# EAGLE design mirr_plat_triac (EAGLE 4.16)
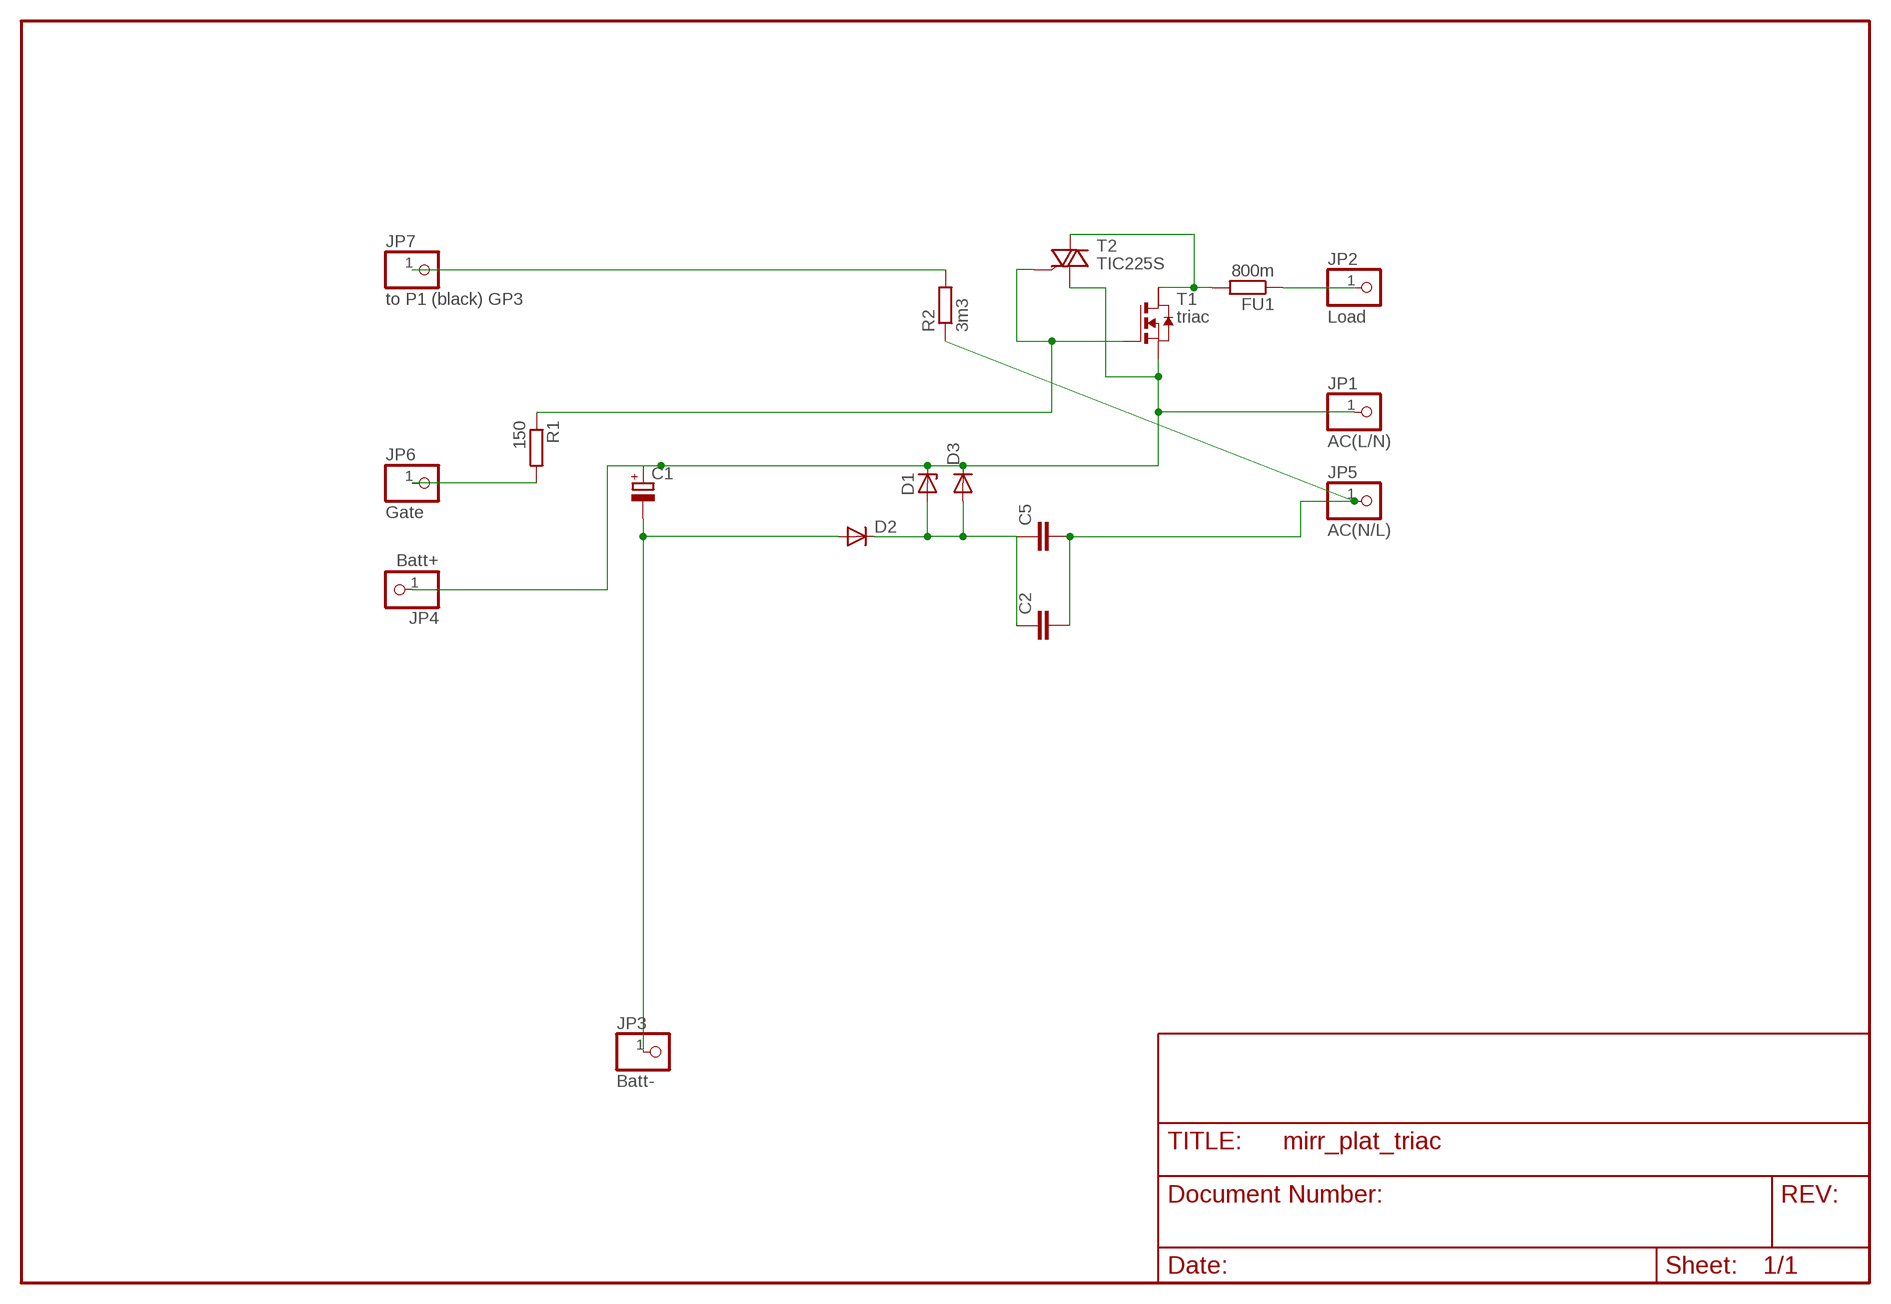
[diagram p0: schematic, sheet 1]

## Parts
C1  CPOL-EUE2,5-6E  [E2,5-6E]
C2  C-EU102-043X133  [C102-043X133]
C5  C-EU050-025X075  [C050-025X075]
D1  ZENER-DIODEDO35Z10  [DO35Z10]
D2  DIODE-MELF-MLL41  [MELF-MLL41]
D3  DIODE-MINIMELF  [MINIMELF]
FU1  800m  R-EU_0204/5  [0204/5]
JP1  AC(L/N)  PINHD-1X1  [1X01]
JP2  Load  PINHD-1X1  [1X01]
JP3  Batt-  PINHD-1X1  [1X01]
JP4  Batt+  PINHD-1X1  [1X01]
JP5  AC(N/L)  PINHD-1X1  [1X01]
JP6  Gate  PINHD-1X1  [1X01]
JP7  to P1 (black) GP3  PINHD-1X1  [1X01]
R1  150  R-EU_R1206  [R1206]
R2  3m3  R-EU_R1206  [R1206]
T1  triac  NMOSSOT223  [SOT223]
T2  TIC225S  [TO220DS]

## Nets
N$1: C1.+ D1.C D3.C JP1.1 JP4.1 T1.3(S) T2.A1
N$2: R1.1 T1.1(G) T2.G
N$3: C1.- D2.A JP3.1
N$4: FU1.1 JP2.1
N$5: JP7.1 R2.2
N$6: C2.1 C5.1 D1.A D2.C D3.A
N$9: FU1.2 T1.2(D) T2.A2
N$11: JP6.1 R1.2
N$37: C2.2 C5.2 JP5.1 R2.1
Unconnected: T1.4(D2)

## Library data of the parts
C1 = rcl(2):CPOL-EU: POLARIZED CAPACITOR, European symbol
C2 = rcl-2:C-EU: CAPACITOR, European symbol
C5 = rcl:C-EU: CAPACITOR, European symbol
D1 = diode-1:ZENER-DIODE: Z-Diode
D2 D3 = diode-1:DIODE-: DIODE
FU1 R1 R2 = rcl:R-EU_: RESISTOR, European symbol
JP1-JP7 = pinhead:PINHD-1X1: PIN HEADER
T1 = zetex:NMOSSOT223: MOS FET
T2 = triac:TIC225S: TRIAC

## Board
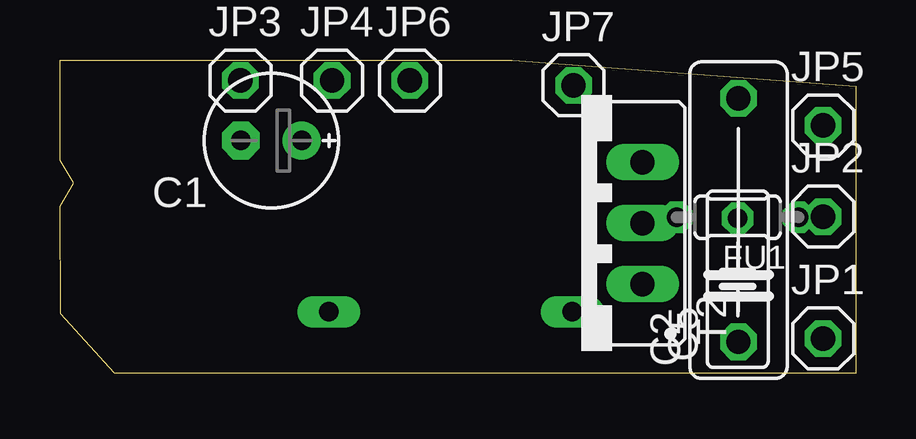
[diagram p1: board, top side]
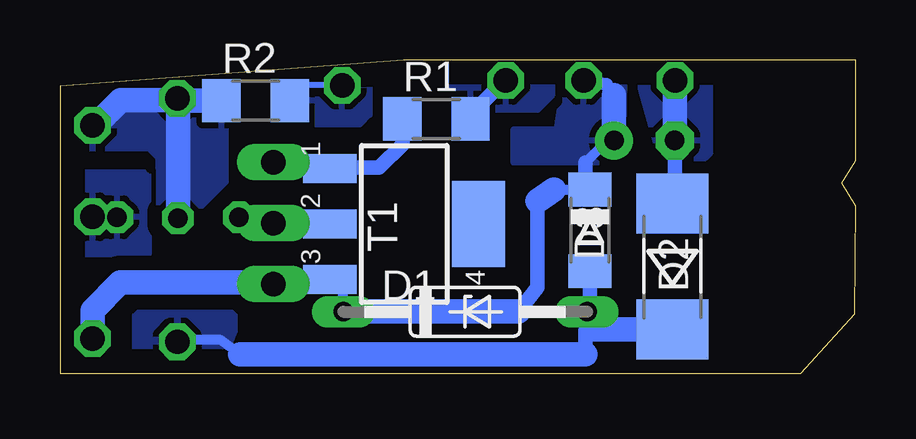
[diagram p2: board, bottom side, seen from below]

Size 33.17 x 13.08 mm. Coordinates in mm from the lower left corner, seen from the top.
Outline: 33.17,0.01 2.29,0 2.29,0.01 0.04,2.48 0,6.99 0.57,7.94 0,8.89 0,13.08 15.18,13.08 18.86,13.08 33.17,12 33.17,0.01
Copper layers (1*16): Top 0.035mm / dielectric 1.5mm / Bottom 0.035mm
Design rules "default": minimum track width 10mil, minimum drill 24mil, track to track 8mil, track to pad 8mil, pad to pad 8mil, via to via 8mil, smd to smd 8mil, copper to edge 40mil, drill to drill 8mil, minimum pad ring 10mil, minimum via ring 8mil, stop-mask expansion 4mil, vias tented up to drill 0mil, thermal gap 10mil

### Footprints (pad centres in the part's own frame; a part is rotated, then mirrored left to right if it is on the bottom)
E2,5-6E = drill 0.813 pad 1.575 round: + -1.27,0 | drill 0.813 pad 1.575 octagon: - 1.27,0
C102-043X133 = drill 1.016 octagon: 1 -5.08,0; 2 5.08,0
C050-025X075 = drill 0.813 octagon: 1 -2.54,0; 2 2.54,0
DO35Z10 = drill 0.813 long: A 5.08,0; C -5.08,0
MELF-MLL41 = smd 2.5 x 3: A 2.625,0; C -2.625,0
MINIMELF = smd 1.4 x 1.8: A 1.7,0; C -1.7,0
0204/5 = drill 0.813 octagon: 1 -2.54,0; 2 2.54,0
1X01 = drill 1.016 octagon: 1 0,0
R1206 = smd 1.6 x 1.803: 1 -1.422,0; 2 1.422,0
SOT223 = smd 1.219 x 2.235: 1 -2.311,-3.099; 2 0,-3.099; 3 2.311,-3.099 | smd 3.6 x 2.2: 4 0,3.099
TO220DS = drill 1.016 long: A1 -2.54,-2.54; A2 0,-2.54; G 2.54,-2.54

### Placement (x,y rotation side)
C1  8.81,9.72 180 top
C2  28.28,6.4 90 top
C5  28.25,3.94 90 top
D1  16.28,2.58 0 bottom
D2  7.64,4.47 90 bottom
D3  11.08,5.98 270 bottom
FU1  28.25,6.52 180 top
JP1  31.81,1.46 0 top
JP2  31.81,6.54 0 top
JP3  7.53,12.23 0 top
JP4  11.34,12.22 0 top
JP5  31.81,10.35 0 top
JP6  14.59,12.22 0 top
JP7  21.41,12.02 0 top
R1  17.48,10.62 0 bottom
R2  25.02,11.39 0 bottom
T1  18.82,6.24 270 bottom
T2  21.74,6.27 90 top

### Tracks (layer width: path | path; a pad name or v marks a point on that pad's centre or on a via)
N$1
  Bottom 0.406: 24.66,3.79 24.26,3.79 24.28,3.81 T2.A1 24.52,3.93 24.66,3.79 | 24.66,3.79 24.33,4.12 T1.3 21.92,4.14 21.86,4.19 21.36,3.69 D1.C 21.45,2.58 21.46,2.59 | 12.58,7.68 D3.C 11.15,7.68 11.26,7.79 | C1.+ 10.08,9.98 11.26,8.79 | JP4.1 10.34,12.11 10.46,11.99 10.08,11.61
  Bottom 0.61: 13.26,7.19 13.26,3.59 14.06,2.59 | 11.26,7.79 11.26,8.79
  Bottom 1.016: JP1.1 31.81,2.64 30.66,3.79 24.66,3.79 | 13.26,7.19 12.58,7.68 | 14.06,2.59 21.46,2.59 | C1.+ 10.08,11.61
  pour Bottom (isolate 0.305, rank 2): 9.66,12.79 9.66,9.79 10.46,8.79 14.26,8.79 14.26,10.19 12.46,10.19 12.06,12.79
N$2
  Bottom 0.254: T1.1 21.82,8.55 21.66,8.39 21.46,8.59
  Bottom 0.406: T2.G 24.44,9.01 24.46,8.99 24.22,8.75 T1.1
  Bottom 0.61: R1.1 18.9,9.55 19.86,8.59 21.46,8.59
N$3
  Bottom 0.406: D2.A 7.64,7.17 7.66,7.19 7.54,7.32 | JP3.1 7.53,12.06 7.46,11.99 7.54,11.92
  Bottom 0.61: 7.54,7.32 C1.-
  Bottom 1.016: C1.- 7.54,11.92
  pour Bottom: 6.06,12.39 8.86,12.39 9.06,12.19 8.26,9.39 8.26,8.99 6.26,8.99 6.06,9.19
N$4
  Bottom 0.406: FU1.1 30.93,6.52 31.06,6.39 31.21,6.54 JP2.1
  pour Bottom (isolate 0.61): 29.66,8.39 32.66,8.39 32.86,8.19 32.86,5.19 32.66,4.99 29.46,4.99 29.46,7.99 29.26,8.19 29.46,8.19
N$5
  Bottom 0.254: R2.2 23.86,11.39 23.23,12.02 JP7.1
  pour Bottom (isolate 0.305): 20.26,12.39 20.26,10.79 20.66,10.39 22.86,10.39 23.06,10.59 23.06,12.59 20.26,12.59
N$6
  Bottom 0.406: 25.66,0.79 26.47,1.4 C5.1 28.25,1.2 28.26,1.19 28.28,1.21 C2.1 | D1.A 11.2,2.13 11.06,1.99 11.26,1.79 | D1.A 11.2,2.25 11.26,2.19 10.92,1.85 | 11.2,2.45 11.26,2.39 | D1.A 11.2,2.45 | 11.2,2.45 11.08,2.57
  Bottom 0.61: 11.26,1.79 11.26,0.79 | 11.08,2.57 D3.A
  Bottom 1.016: 11.26,0.79 25.66,0.79 | D2.C 10.92,1.85
  pour Bottom (isolate 0.61): 25.86,1.79 25.86,2.39 26.26,2.79 29.66,2.79 30.06,2.39 30.06,0.59 29.86,0.39 26.46,0.39
N$9
  Bottom 0.406: T1.2 24.46,6.39 T2.A2 25.58,6.47 25.66,6.39 25.71,6.44 FU1.2
N$11
  Bottom 0.254: 16.06,10.79 16.06,10.78 R1.2 | JP6.1 14.63,12.22
  Bottom 0.61: 14.63,12.22 16.06,10.79
  pour Bottom (isolate 0.305): 12.66,12.79 12.66,11.59 13.26,10.99 16.86,10.99 16.86,12.79 16.66,12.99
N$37
  Bottom 0.406: 28.25,11.38 28.26,11.39 | 28.26,11.39 28.28,11.41 C2.2 | 28.26,11.39 | 31.86,10.19 31.81,10.24 JP5.1
  Bottom 1.016: C5.2 28.25,11.38 | 28.26,11.39 R2.1 | 28.28,11.41 30.64,11.41 31.81,10.24
  pour Bottom (rank 2): 26.26,11.59 26.26,7.99 27.46,6.79 28.86,6.79 29.06,6.99 29.06,8.99 29.46,9.39 32.26,9.39 32.46,9.19 32.46,11.59 32.26,11.79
